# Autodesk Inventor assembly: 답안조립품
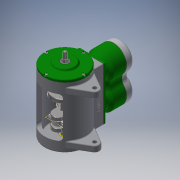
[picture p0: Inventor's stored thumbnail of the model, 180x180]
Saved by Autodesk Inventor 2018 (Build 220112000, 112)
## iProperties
Created: 2019-08
Part Number: 답안조립품
Document SubType Name: Assembly
Designer: Administrator
Author: Administrator
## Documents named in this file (18)
- C:\Users\Administrator\Desktop\390804V1046\답안조립품.iam
- C:\Users\Administrator\Desktop\390804V1046\본체.ipt
- C:\Users\Administrator\Desktop\390804V1046\베어링 12 x 28 x 8.ipt
- C:\Users\Administrator\Desktop\390804V1046\크랭크축.ipt
- C:\Users\Administrator\Desktop\390804V1046\앞커버.ipt
- C:\Users\Administrator\Desktop\390804V1046\오일 실 12 25 7.ipt
- C:\Users\Administrator\Desktop\390804V1046\볼트 M4 x 8.ipt
- C:\Users\Administrator\Desktop\390804V1046\실린더 개스킷.ipt
- C:\Users\Administrator\Desktop\390804V1046\실린더.ipt
- C:\Users\Administrator\Desktop\390804V1046\실린더헤드 개스킷.ipt
- C:\Users\Administrator\Desktop\390804V1046\볼트 M5 x 20.ipt
- C:\Users\Administrator\Desktop\390804V1046\실린더헤드.ipt
- C:\Users\Administrator\Desktop\390804V1046\커넥팅로드 엔드.ipt
- C:\Users\Administrator\Desktop\390804V1046\커넥팅로드.ipt
- C:\Users\Administrator\Desktop\390804V1046\피스톤.ipt
- C:\Users\Administrator\Desktop\390804V1046\피스톤핀.ipt
- C:\Users\Administrator\Desktop\390804V1046\너트 M4.ipt
- C:\Users\Administrator\Desktop\390804V1046\육각 머리 볼트 M4 x 16.ipt
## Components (4 placed, 2 different names)
1. 피스톤:1
2. 피스톤핀:1
3. 피스톤:2
4. 피스톤핀:2
